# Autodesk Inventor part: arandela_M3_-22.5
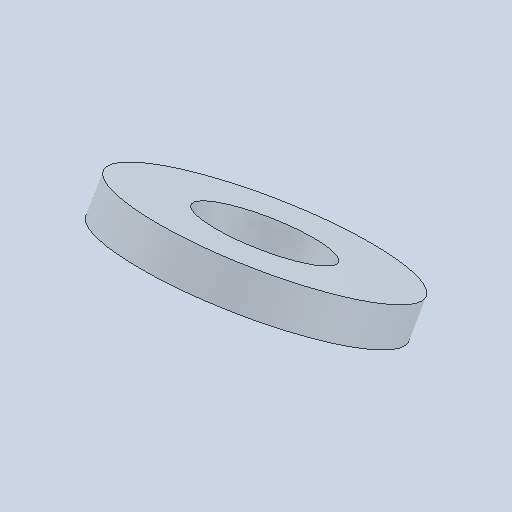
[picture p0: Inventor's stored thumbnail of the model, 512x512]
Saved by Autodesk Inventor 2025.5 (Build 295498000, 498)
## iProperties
Created: 2026-10
Part Number: arandela_M3_-22.5
Material: Genérico
Document SubType Name: Modeling
Designer: Luis M
Density: 1 g/cm^3
Appearance: Valor por defecto
Author: Luis M
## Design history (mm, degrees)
feature "Base1"
node "Sólido1"
